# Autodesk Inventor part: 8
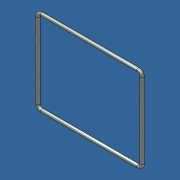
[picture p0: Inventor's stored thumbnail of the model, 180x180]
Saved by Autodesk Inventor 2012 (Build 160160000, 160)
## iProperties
Created: 2013-04
Part Number: 8
Material: Steel
Document SubType Name: Modeling
Designer: Admin
Density: 7.85 g/cm^3
Mass: 44.925 g
Surface Area: 57.2293 cm^2
Volume: 5.72293 cm^3
Author: Admin
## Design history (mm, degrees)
node "81"
node "8"
node "Base1"
